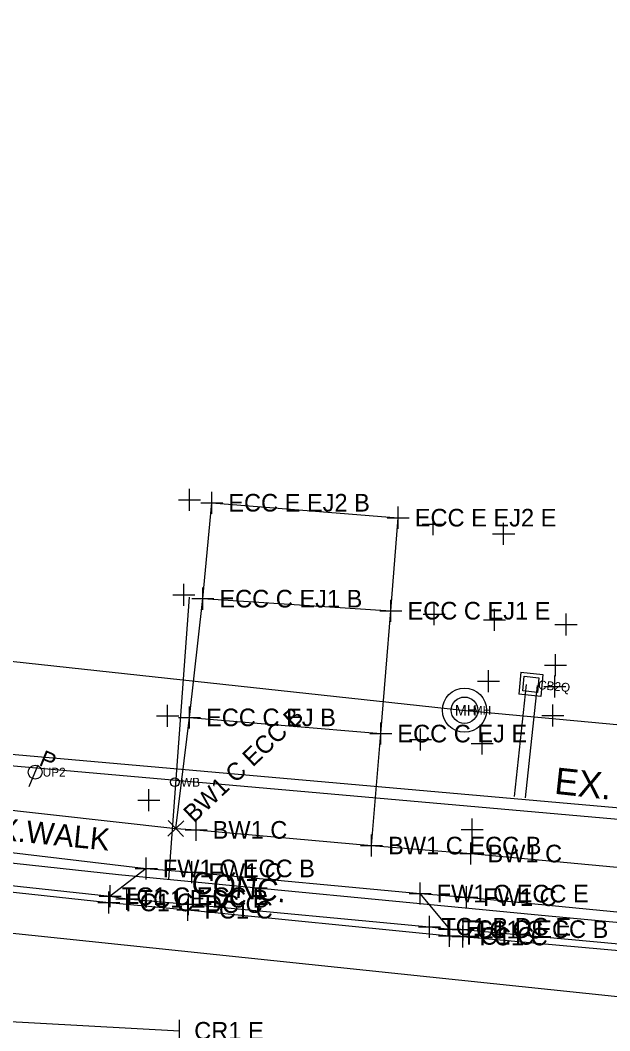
# Model space of a CAD drawing. Extents: x 1363693 to 1365209, y 422201 to 424153.
# Drawn here: x 1364479.4 to 1364532.9, y 423089.8 to 423181.5 of the extents above; entities that cross this region are included whole.
import ezdxf

# ---------------------------------------------------------------- set-up
doc = ezdxf.new("R2010")
doc.units = 0
for name, color, linetype in [('BASELINE-CL-RW', 7, 'Continuous'), ('DR_X_Cells', 7, 'Continuous'), ('DR_X_Storm_Sewer', 7, 'Continuous'), ('DR_X_Text', 7, 'Continuous'), ('O-ALGN-BASELINE-WERK-CL-RW', 7, 'Continuous'), ('O-ALGN-TEXT-BASELINE-WERK-CL-RW', 7, 'Continuous'), ('OWNERS', 7, 'Continuous'), ('PV_X_Driveway', 7, 'Continuous'), ('PV_X_Joint', 7, 'Continuous'), ('RD_X_Text', 7, 'Continuous'), ('SV_X_Original_Ground', 7, 'Continuous'), ('SV_X_Shot_Marker', 7, 'Continuous'), ('UT_X_Misc_Cells', 7, 'Continuous'), ('UT_X_Sanitary_Line', 7, 'Continuous'), ('UT_X_Unknown_Cells', 7, 'Continuous'), ('UT_X_Water', 7, 'Continuous'), ('UT_X_Water_Text', 7, 'Continuous')]:
    doc.layers.add(name, color=color, linetype=linetype)

msp = doc.modelspace()

# ---------------------------------------------------------------- linework, layer by layer
at = {"layer": 'BASELINE-CL-RW'}
for p, q in [((1364489.077, 423101.82), (1364494.658, 423101.337)), ((1364494.658, 423101.337), (1364516.524, 423099.283))]:
    msp.add_line(p, q, dxfattribs=at)
for points in [[(1364455.696, 423105.51), (1364457.148, 423105.352), (1364469.896, 423103.962), (1364487.56, 423102.049), (1364489.077, 423101.82)], [(1364489.077, 423101.82), (1364494.658, 423101.337), (1364516.524, 423099.283)], [(1364516.524, 423099.283), (1364518.355, 423099.064), (1364519.579, 423099.02), (1364540.917, 423097.06), (1364542.021, 423096.953)]]:
    msp.add_lwpolyline(points, dxfattribs=at)
at = {"layer": 'DR_X_Cells'}
for p, q in [((1364524.808, 423122.367), (1364524.615, 423120.376)), ((1364524.808, 423122.367), (1364526.799, 423122.174)), ((1364524.979, 423120.676), (1364525.108, 423122.003)), ((1364525.108, 423122.003), (1364526.435, 423121.874)), ((1364526.435, 423121.874), (1364526.306, 423120.547)), ((1364526.799, 423122.174), (1364526.606, 423120.183)), ((1364526.306, 423120.547), (1364524.979, 423120.676)), ((1364526.606, 423120.183), (1364524.615, 423120.376))]:
    msp.add_line(p, q, dxfattribs=at)
at = {"layer": 'DR_X_Storm_Sewer'}
for p, q in [((1364525.282, 423121.273), (1364524.21, 423111.084)), ((1364526.276, 423121.169), (1364525.204, 423110.979))]:
    msp.add_line(p, q, dxfattribs=at)
for points in [[(1364582.765, 423092.444), (1364570.467, 423106.795), (1364396.66, 423122.141)], [(1364396.572, 423121.144), (1364569.973, 423105.835), (1364582.006, 423091.794)]]:
    msp.add_lwpolyline(points, dxfattribs=at)
at = {"layer": 'O-ALGN-BASELINE-WERK-CL-RW'}
msp.add_lwpolyline([(1364345.02, 423104.847), (1364369.674, 423102.16), (1364393.972, 423099.432), (1364419.048, 423096.561), (1364443.312, 423093.925), (1364451.526, 423093.036), (1364468.627, 423091.238), (1364493.852, 423089.842)], dxfattribs=at)
at = {"layer": 'O-ALGN-TEXT-BASELINE-WERK-CL-RW'}
for points in [[(1364346.419, 423124.233), (1364371.073, 423121.613), (1364377.993, 423120.886), (1364394.176, 423119.014), (1364395.909, 423118.85), (1364420.904, 423116.17), (1364432.793, 423114.854), (1364445.849, 423113.459), (1364451.029, 423112.833), (1364470.499, 423110.769), (1364493.516, 423108.187), (1364495.355, 423108.072), (1364511.265, 423106.648), (1364520.276, 423105.924), (1364545.163, 423103.611)], [(1364345.955, 423120.338), (1364370.704, 423117.73), (1364377.302, 423116.907), (1364393.837, 423115.175), (1364395.564, 423115.012), (1364420.484, 423112.241), (1364428.47, 423111.311), (1364445.436, 423109.533), (1364454.484, 423108.631), (1364470.191, 423107.015), (1364490.846, 423104.574), (1364494.981, 423104.245), (1364515.675, 423102.289), (1364519.894, 423101.964), (1364544.07, 423099.593)]]:
    msp.add_lwpolyline(points, dxfattribs=at)
at = {"layer": 'OWNERS'}
for p, q in [((1364490.846, 423104.574), (1364487.56, 423102.049)), ((1364518.355, 423099.064), (1364515.675, 423102.289))]:
    msp.add_line(p, q, dxfattribs=at)
msp.add_lwpolyline([(1364320.806, 423119.405), (1364345.561, 423116.767), (1364370.383, 423114.062), (1364373.909, 423113.642), (1364396.32, 423111.238), (1364420.061, 423108.761), (1364425.197, 423108.148), (1364444.961, 423106.049), (1364457.021, 423104.742), (1364469.814, 423103.394), (1364487.439, 423101.485), (1364494.624, 423100.826), (1364518.333, 423098.452), (1364519.558, 423098.394), (1364540.805, 423096.489), (1364544.341, 423096.157), (1364569.726, 423093.884), (1364581.491, 423092.909)], dxfattribs=at)
at = {"layer": 'PV_X_Driveway'}
for points in [[(1364493.516, 423108.187), (1364494.766, 423118.277), (1364495.974, 423129.049), (1364496.776, 423137.752)], [(1364511.265, 423106.648), (1364512.11, 423116.81), (1364513.03, 423127.956), (1364513.689, 423136.396)]]:
    msp.add_lwpolyline(points, dxfattribs=at)
at = {"layer": 'PV_X_Joint'}
for p, q in [((1364496.776, 423137.752), (1364513.689, 423136.396)), ((1364495.974, 423129.049), (1364513.03, 423127.956)), ((1364494.766, 423118.277), (1364512.11, 423116.81))]:
    msp.add_line(p, q, dxfattribs=at)
at = {"layer": 'SV_X_Original_Ground'}
for p, q in [((1364494.762, 423137.028), (1364494.762, 423139.028)), ((1364493.762, 423138.028), (1364495.762, 423138.028)), ((1364516.87, 423134.807), (1364516.87, 423136.807)), ((1364515.87, 423135.807), (1364517.87, 423135.807)), ((1364523.247, 423133.92), (1364523.247, 423135.92)), ((1364522.247, 423134.92), (1364524.247, 423134.92)), ((1364494.247, 423128.399), (1364494.247, 423130.399)), ((1364493.247, 423129.399), (1364495.247, 423129.399)), ((1364516.952, 423126.633), (1364516.952, 423128.633)), ((1364522.413, 423126.117), (1364522.413, 423128.117)), ((1364515.952, 423127.633), (1364517.952, 423127.633)), ((1364521.413, 423127.117), (1364523.413, 423127.117)), ((1364528.903, 423125.717), (1364528.903, 423127.717)), ((1364527.903, 423126.717), (1364529.903, 423126.717)), ((1364527.96, 423122.012), (1364527.96, 423124.012)), ((1364521.867, 423120.567), (1364521.867, 423122.567)), ((1364526.96, 423123.012), (1364528.96, 423123.012)), ((1364520.867, 423121.567), (1364522.867, 423121.567)), ((1364527.877, 423120.075), (1364527.877, 423122.075)), ((1364526.877, 423121.075), (1364528.877, 423121.075)), ((1364492.782, 423117.412), (1364492.782, 423119.412)), ((1364527.709, 423117.444), (1364527.709, 423119.444)), ((1364491.782, 423118.412), (1364493.782, 423118.412)), ((1364526.709, 423118.444), (1364528.709, 423118.444)), ((1364515.708, 423115.272), (1364515.708, 423117.272)), ((1364521.308, 423114.903), (1364521.308, 423116.903)), ((1364514.708, 423116.272), (1364516.708, 423116.272)), ((1364520.308, 423115.903), (1364522.308, 423115.903)), ((1364491.081, 423109.753), (1364491.081, 423111.753)), ((1364490.081, 423110.753), (1364492.081, 423110.753)), ((1364520.385, 423107.104), (1364520.385, 423109.104)), ((1364519.385, 423108.104), (1364521.385, 423108.104)), ((1364493.852, 423088.842), (1364493.852, 423090.842))]:
    msp.add_line(p, q, dxfattribs=at)
at = {"layer": 'SV_X_Shot_Marker'}
for p, q in [((1364496.776, 423136.752), (1364496.776, 423138.752)), ((1364495.776, 423137.752), (1364497.776, 423137.752)), ((1364513.689, 423135.396), (1364513.689, 423137.396)), ((1364512.689, 423136.396), (1364514.689, 423136.396)), ((1364495.974, 423128.049), (1364495.974, 423130.049)), ((1364494.974, 423129.049), (1364496.974, 423129.049)), ((1364513.03, 423126.956), (1364513.03, 423128.956)), ((1364512.03, 423127.956), (1364514.03, 423127.956)), ((1364494.766, 423117.277), (1364494.766, 423119.277)), ((1364493.766, 423118.277), (1364495.766, 423118.277)), ((1364512.11, 423115.81), (1364512.11, 423117.81)), ((1364511.11, 423116.81), (1364513.11, 423116.81)), ((1364492.791, 423107.498), (1364494.241, 423108.876)), ((1364494.205, 423107.462), (1364492.827, 423108.912)), ((1364495.355, 423107.072), (1364495.355, 423109.072)), ((1364494.355, 423108.072), (1364496.355, 423108.072)), ((1364511.265, 423105.648), (1364511.265, 423107.648)), ((1364520.276, 423104.924), (1364520.276, 423106.924)), ((1364510.265, 423106.648), (1364512.265, 423106.648)), ((1364519.276, 423105.924), (1364521.276, 423105.924)), ((1364490.846, 423103.574), (1364490.846, 423105.574)), ((1364494.981, 423103.245), (1364494.981, 423105.245)), ((1364489.846, 423104.574), (1364491.846, 423104.574)), ((1364493.981, 423104.245), (1364495.981, 423104.245)), ((1364515.675, 423101.289), (1364515.675, 423103.289)), ((1364487.439, 423100.485), (1364487.439, 423102.485)), ((1364487.56, 423101.049), (1364487.56, 423103.049)), ((1364489.077, 423100.82), (1364489.077, 423102.82)), ((1364494.658, 423100.337), (1364494.658, 423102.337)), ((1364514.675, 423102.289), (1364516.675, 423102.289)), ((1364519.894, 423100.964), (1364519.894, 423102.964)), ((1364486.439, 423101.485), (1364488.439, 423101.485)), ((1364486.56, 423102.049), (1364488.56, 423102.049)), ((1364488.077, 423101.82), (1364490.077, 423101.82)), ((1364493.658, 423101.337), (1364495.658, 423101.337)), ((1364494.624, 423099.826), (1364494.624, 423101.826)), ((1364518.894, 423101.964), (1364520.894, 423101.964)), ((1364493.624, 423100.826), (1364495.624, 423100.826)), ((1364516.524, 423098.283), (1364516.524, 423100.283)), ((1364518.355, 423098.064), (1364518.355, 423100.064)), ((1364519.579, 423098.02), (1364519.579, 423100.02)), ((1364515.524, 423099.283), (1364517.524, 423099.283)), ((1364517.355, 423099.064), (1364519.355, 423099.064)), ((1364518.333, 423097.452), (1364518.333, 423099.452)), ((1364518.579, 423099.02), (1364520.579, 423099.02)), ((1364519.558, 423097.394), (1364519.558, 423099.394)), ((1364517.333, 423098.452), (1364519.333, 423098.452)), ((1364518.558, 423098.394), (1364520.558, 423098.394))]:
    msp.add_line(p, q, dxfattribs=at)
at = {"layer": 'UT_X_Sanitary_Line'}
msp.add_lwpolyline([(1364693.403, 423102.755), (1364519.502, 423118.915), (1364254.219, 423147.686), (1364120.797, 423178.489), (1364080.299, 423181.531), (1364078.775, 423157.716), (1364068.834, 423074.38), (1364132.412, 423042.257), (1364111.643, 422924.766), (1364032.031, 422957.358)], dxfattribs=at)
at = {"layer": 'UT_X_Unknown_Cells'}
msp.add_line((1364480.228, 423112.015), (1364481.031, 423113.96), dxfattribs=at)
for centre, radius in [((1364519.699, 423118.924), 2), ((1364519.699, 423118.924), 1.2), ((1364480.762, 423113.309), 0.63)]:
    msp.add_circle(centre, radius, dxfattribs=at)
at = {"layer": 'UT_X_Water'}
msp.add_line((1364492.873, 423103.562), (1364494.749, 423129.17), dxfattribs=at)
for points in [[(1363797.978, 423165.496), (1364047.142, 423141.995), (1364047.135, 423142.005), (1364251.213, 423122.543), (1364692.365, 423076.33)], [(1364199.274, 423140.77), (1364264.462, 423134.201), (1364302.919, 423131.268), (1364302.919, 423124.149), (1364488.328, 423104.035), (1364526.667, 423100.332), (1364656.437, 423088.194), (1364694.224, 423084.44)]]:
    msp.add_lwpolyline(points, dxfattribs=at)
msp.add_circle((1364493.431, 423112.392), 0.4, dxfattribs=at)

# ---------------------------------------------------------------- texts
at = {"layer": 'DR_X_Text'}
for s, height, rotation, p in [('CB2Q', 0.8, 354.47285, (1364526.337, 423120.85)), ('EX. 12" STM.', 2.4, 353.87176, (1364527.778, 423111.357))]:
    msp.add_text(s, height=height, rotation=rotation, dxfattribs=at).set_placement(p)
at = {"layer": 'RD_X_Text'}
for s, p in [('EX.WALK', (1364475.592, 423107.361)), ('CONC.', (1364494.867, 423102.327))]:
    msp.add_text(s, height=2, rotation=354.30306, dxfattribs=at).set_placement(p)
at = {"layer": 'SV_X_Original_Ground'}
msp.add_text('CR1 E', height=1.6, dxfattribs=at).set_placement((1364495.189, 423089.042))
at = {"layer": 'SV_X_Shot_Marker'}
for s, p in [('ECC E EJ2 B', (1364498.276, 423136.952)), ('ECC E EJ2 E', (1364515.189, 423135.596)), ('ECC C EJ1 B', (1364497.474, 423128.249)), ('ECC C EJ1 E', (1364514.53, 423127.156)), ('ECC C EJ B', (1364496.266, 423117.477)), ('ECC C EJ E', (1364513.61, 423116.01)), ('BW1 C', (1364496.855, 423107.272)), ('BW1 C ECC B', (1364512.765, 423105.848)), ('BW1 C', (1364521.776, 423105.124)), ('FW1 C ECC B', (1364492.346, 423103.774)), ('FW1 C', (1364496.481, 423103.445)), ('TC1 C ECC E', (1364488.631, 423101.249)), ('FC1 C', (1364488.939, 423100.685)), ('TC1 E DC B', (1364490.148, 423101.02)), ('FW1 C ECC E', (1364517.175, 423101.489)), ('FW1 C', (1364521.394, 423101.164)), ('FC1 C', (1364496.124, 423100.026)), ('DC C', (1364496.158, 423100.537)), ('TC1 B DC E', (1364517.595, 423098.483)), ('TC1 C ECC B', (1364519.426, 423098.264)), ('TC1 C', (1364520.65, 423098.22)), ('FC1 C', (1364519.833, 423097.652)), ('FC1 C', (1364521.058, 423097.594))]:
    msp.add_text(s, height=1.6, dxfattribs=at).set_placement(p)
msp.add_text('BW1 C ECC B', height=1.6, rotation=43.54925, dxfattribs=at).set_placement((1364495.154, 423108.641))
at = {"layer": 'UT_X_Misc_Cells'}
for s, p in [('MH', (1364520.449, 423118.524)), ('UP2', (1364481.451, 423112.909))]:
    msp.add_text(s, height=0.8, dxfattribs=at).set_placement(p)
at = {"layer": 'UT_X_Unknown_Cells'}
msp.add_text('MH', height=0.96, dxfattribs=at).set_placement((1364518.83, 423118.444))
msp.add_text('P', height=1.503, rotation=337.58271, dxfattribs=at).set_placement((1364481.031, 423113.96))
at = {"layer": 'UT_X_Water_Text'}
msp.add_text('WB', height=0.8, dxfattribs=at).set_placement((1364493.991, 423111.992))

doc.saveas('drawing.dxf')
